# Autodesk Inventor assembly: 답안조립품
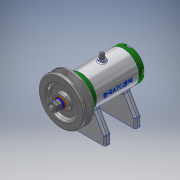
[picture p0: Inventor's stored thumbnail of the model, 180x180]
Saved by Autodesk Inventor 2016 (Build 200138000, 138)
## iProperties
Created: 2018-05
Part Number: 답안조립품
Material: 일반
Document SubType Name: Assembly
Designer: USER
Author: USER
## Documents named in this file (16)
- C:\Users\USER\Desktop\480507v1018\답안조립품.iam
- C:\Users\USER\Desktop\480507v1018\본체.ipt
- C:\Users\USER\Desktop\480507v1018\베어링 6002.ipt
- C:\Users\USER\Desktop\480507v1018\축.ipt
- C:\Users\USER\Desktop\480507v1018\뒤커버.ipt
- C:\Users\USER\Desktop\480507v1018\볼트 M4x12.ipt
- C:\Users\USER\Desktop\480507v1018\앞커버.ipt
- C:\Users\USER\Desktop\480507v1018\오일 실 15 25 7.ipt
- C:\Users\USER\Desktop\480507v1018\니플 M6x0.75.ipt
- C:\Users\USER\Desktop\480507v1018\볼트 M6x8.ipt
- C:\Users\USER\Desktop\480507v1018\와셔 6x11.5.ipt
- C:\Users\USER\Desktop\480507v1018\V벨트풀리.ipt
- C:\Users\USER\Desktop\480507v1018\키 3x3x12.ipt
- C:\Users\USER\Desktop\480507v1018\와셔 8x17.ipt
- C:\Users\USER\Desktop\480507v1018\스프링와셔 8.ipt
- C:\Users\USER\Desktop\480507v1018\너트 M8.ipt
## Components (1 placed, 1 different names)
1. V벨트풀리:1
